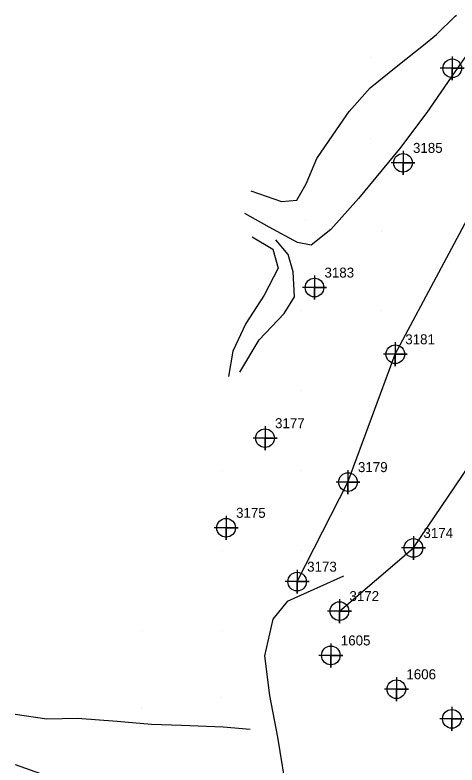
# Model space of a CAD drawing. Extents: x 2062781 to 2066835, y 358981 to 366501.
# Drawn here: x 2063958.7 to 2064069.5, y 361856.4 to 362044.4 of the extents above; entities that cross this region are included whole.
import ezdxf

# ---------------------------------------------------------------- set-up
doc = ezdxf.new("R2010")
doc.units = 0
for name, color, linetype in [('Exist DTM Breakline', 7, 'Continuous'), ('Exist DTM Breakline Cogo Number', 7, 'Continuous'), ('Exist DTM Breakline Cogo Point CELL', 7, 'Continuous'), ('Exist DTM Regular Point CELL', 7, 'Continuous'), ('Exist DTM Regular Point Cogo Number', 7, 'Continuous'), ('Exist DTM Ridgeline', 7, 'Continuous'), ('Exist DTM Ridgeline Cogo Number', 7, 'Continuous'), ('Exist DTM Ridgeline Cogo Point CELL', 7, 'Continuous'), ('PH Exist DTM Breakline', 7, 'Continuous'), ('PH Exist DTM Point', 7, 'Continuous')]:
    doc.layers.add(name, color=color, linetype=linetype)

msp = doc.modelspace()

# ---------------------------------------------------------------- linework, layer by layer
at = {"layer": 'Exist DTM Breakline'}
msp.add_lwpolyline([(2064029.46, 361902.4), (2064042.2, 361927.36), (2064054.07, 361959.4), (2064073.45, 361995.69), (2064101.12, 362020.33), (2064117.15, 362026.42)], dxfattribs=at)
at = {"layer": 'Exist DTM Breakline Cogo Point CELL'}
for points in [[(2064054.07, 361962.4), (2064054.07, 361956.4), (2064054.07, 361959.4), (2064057.07, 361959.4), (2064051.07, 361959.4)], [(2064054.07, 361962.4), (2064054.07, 361956.4), (2064054.07, 361959.4), (2064057.07, 361959.4), (2064051.07, 361959.4)], [(2064054.07, 361962.4), (2064054.07, 361956.4), (2064054.07, 361959.4), (2064057.07, 361959.4), (2064051.07, 361959.4)], [(2064042.2, 361930.36), (2064042.2, 361924.36), (2064042.2, 361927.36), (2064045.2, 361927.36), (2064039.2, 361927.36)], [(2064042.2, 361930.36), (2064042.2, 361924.36), (2064042.2, 361927.36), (2064045.2, 361927.36), (2064039.2, 361927.36)], [(2064042.2, 361930.36), (2064042.2, 361924.36), (2064042.2, 361927.36), (2064045.2, 361927.36), (2064039.2, 361927.36)], [(2064029.46, 361905.4), (2064029.46, 361899.4), (2064029.46, 361902.4), (2064032.46, 361902.4), (2064026.46, 361902.4)], [(2064029.46, 361905.4), (2064029.46, 361899.4), (2064029.46, 361902.4), (2064032.46, 361902.4), (2064026.46, 361902.4)], [(2064029.46, 361905.4), (2064029.46, 361899.4), (2064029.46, 361902.4), (2064032.46, 361902.4), (2064026.46, 361902.4)]]:
    msp.add_lwpolyline(points, dxfattribs=at)
for centre in [(2064054.07, 361959.4), (2064054.07, 361959.4), (2064054.07, 361959.4), (2064042.2, 361927.36), (2064042.2, 361927.36), (2064042.2, 361927.36), (2064029.46, 361902.4), (2064029.46, 361902.4), (2064029.46, 361902.4)]:
    msp.add_circle(centre, 2.34, dxfattribs=at)
at = {"layer": 'Exist DTM Regular Point CELL'}
for points in [[(2064068.35, 362034.08), (2064068.35, 362028.08), (2064068.35, 362031.08), (2064071.35, 362031.08), (2064065.35, 362031.08)], [(2064056, 362010.38), (2064056, 362004.38), (2064056, 362007.38), (2064059, 362007.38), (2064053, 362007.38)], [(2064033.8, 361979.12), (2064033.8, 361973.12), (2064033.8, 361976.12), (2064036.8, 361976.12), (2064030.8, 361976.12)], [(2064021.4, 361941.37), (2064021.4, 361935.37), (2064021.4, 361938.37), (2064024.4, 361938.37), (2064018.4, 361938.37)], [(2064011.63, 361918.9), (2064011.63, 361912.9), (2064011.63, 361915.9), (2064014.63, 361915.9), (2064008.63, 361915.9)], [(2064037.9, 361886.91), (2064037.9, 361880.91), (2064037.9, 361883.91), (2064040.9, 361883.91), (2064034.9, 361883.91)], [(2064054.34, 361878.43), (2064054.34, 361872.43), (2064054.34, 361875.43), (2064057.34, 361875.43), (2064051.34, 361875.43)], [(2064068.25, 361871), (2064068.25, 361865), (2064068.25, 361868), (2064071.25, 361868), (2064065.25, 361868)]]:
    msp.add_lwpolyline(points, dxfattribs=at)
for centre in [(2064068.35, 362031.08), (2064056, 362007.38), (2064033.8, 361976.12), (2064021.4, 361938.37), (2064011.63, 361915.9), (2064037.9, 361883.91), (2064054.34, 361875.43), (2064068.25, 361868)]:
    msp.add_circle(centre, 2.34, dxfattribs=at)
at = {"layer": 'Exist DTM Ridgeline'}
msp.add_lwpolyline([(2064040.06, 361895.02), (2064058.62, 361910.84), (2064072.66, 361931.62), (2064084.88, 361946.07), (2064096.39, 361965.27), (2064109.04, 361979.15), (2064128.44, 361984.19), (2064155.63, 361985.77), (2064168.96, 361977.42), (2064180.57, 361975.17)], dxfattribs=at)
at = {"layer": 'Exist DTM Ridgeline Cogo Point CELL'}
for points in [[(2064058.62, 361913.84), (2064058.62, 361907.84), (2064058.62, 361910.84), (2064061.62, 361910.84), (2064055.62, 361910.84)], [(2064058.62, 361913.84), (2064058.62, 361907.84), (2064058.62, 361910.84), (2064061.62, 361910.84), (2064055.62, 361910.84)], [(2064058.62, 361913.84), (2064058.62, 361907.84), (2064058.62, 361910.84), (2064061.62, 361910.84), (2064055.62, 361910.84)], [(2064040.06, 361898.02), (2064040.06, 361892.02), (2064040.06, 361895.02), (2064043.06, 361895.02), (2064037.06, 361895.02)], [(2064040.06, 361898.02), (2064040.06, 361892.02), (2064040.06, 361895.02), (2064043.06, 361895.02), (2064037.06, 361895.02)], [(2064040.06, 361898.02), (2064040.06, 361892.02), (2064040.06, 361895.02), (2064043.06, 361895.02), (2064037.06, 361895.02)]]:
    msp.add_lwpolyline(points, dxfattribs=at)
for centre in [(2064058.62, 361910.84), (2064058.62, 361910.84), (2064058.62, 361910.84), (2064040.06, 361895.02), (2064040.06, 361895.02), (2064040.06, 361895.02)]:
    msp.add_circle(centre, 2.34, dxfattribs=at)
at = {"layer": 'PH Exist DTM Breakline'}
for points in [[(2064017.8, 362000.4), (2064025.52, 361997.73), (2064029.41, 361998.04), (2064031.67, 362002.08), (2064034.41, 362008.49), (2064039.31, 362015.66), (2064042.46, 362020.28), (2064047.8, 362026.18), (2064054.72, 362031.82), (2064061.13, 362036.91), (2064064.39, 362039.53), (2064069.08, 362044.14), (2064069.42, 362044.44)], [(2064076.6, 362041.05), (2064068.96, 362030.17), (2064061.97, 362020.04), (2064055.1, 362010.92), (2064044.83, 361998.43), (2064037.92, 361990.68), (2064032.93, 361986.74), (2064029.56, 361987.4), (2064022.45, 361991.28), (2064016.31, 361994.67)], [(2064018.16, 361988.86), (2064023.34, 361985.71), (2064024.69, 361981.02), (2064021.19, 361974.19), (2064016.62, 361967.14), (2064013.31, 361960.21), (2064012.24, 361953.8)], [(2064015.07, 361954.92), (2064019.92, 361963.02), (2064026.16, 361969.59), (2064028.75, 361973.82), (2064028.44, 361980.02), (2064027.19, 361984.42), (2064024.11, 361988.11)], [(2064041.05, 361903.75), (2064026.97, 361897.39), (2064023.31, 361892.98), (2064021.23, 361883.8), (2064022.49, 361873.87), (2064024.56, 361863.41), (2064026.93, 361848.54)], [(2063958.73, 361869.22), (2063966.67, 361868.02), (2063974.38, 361868.17), (2063984.31, 361867.45), (2063992.89, 361866.65), (2064000.41, 361866.42), (2064010.88, 361865.98), (2064017.7, 361865.46)], [(2063958.69, 361856.52), (2063965.12, 361854.29), (2063970, 361849.19), (2063976.27, 361846.4), (2063983.34, 361846.23), (2063992.71, 361842.97), (2064001.18, 361842.42), (2064010.69, 361844.81), (2064018.76, 361849.67)]]:
    msp.add_lwpolyline(points, dxfattribs=at)
at = {"layer": 'PH Exist DTM Point'}
for p, q in [((2064047.95, 362033.85), (2064047.95, 362033.85)), ((2064047.95, 362013.47), (2064047.95, 362013.47)), ((2064031.43, 361993.3), (2064031.43, 361993.3)), ((2064050.65, 361990.27), (2064050.65, 361990.27)), ((2064030.65, 361970.27), (2064030.65, 361970.27)), ((2064050.65, 361970.27), (2064050.65, 361970.27)), ((2064030.65, 361950.27), (2064030.65, 361950.27)), ((2064010.65, 361930.27), (2064010.65, 361930.27)), ((2064030.65, 361930.27), (2064030.65, 361930.27)), ((2064010.65, 361910.27), (2064010.65, 361910.27)), ((2064030.65, 361910.27), (2064030.65, 361910.27)), ((2063990.63, 361890.24), (2063990.63, 361890.24)), ((2064010.65, 361890.27), (2064010.65, 361890.27)), ((2064010.51, 361873.38), (2064010.51, 361873.38)), ((2063990.48, 361870.93), (2063990.48, 361870.93))]:
    msp.add_line(p, q, dxfattribs=at)

# ---------------------------------------------------------------- texts
at = {"layer": 'Exist DTM Breakline Cogo Number'}
for s, p in [('3181', (2064056.57, 361961.9)), ('3181', (2064056.57, 361961.9)), ('3181', (2064056.57, 361961.9)), ('3179', (2064044.7, 361929.86)), ('3179', (2064044.7, 361929.86)), ('3179', (2064044.7, 361929.86)), ('3173', (2064031.96, 361904.9)), ('3173', (2064031.96, 361904.9)), ('3173', (2064031.96, 361904.9))]:
    msp.add_text(s, height=2.5, dxfattribs=at).set_placement(p)
at = {"layer": 'Exist DTM Regular Point Cogo Number'}
for s, p in [('3185', (2064058.5, 362009.88)), ('3185', (2064058.5, 362009.88)), ('3185', (2064058.5, 362009.88)), ('3183', (2064036.3, 361978.62)), ('3183', (2064036.3, 361978.62)), ('3183', (2064036.3, 361978.62)), ('3177', (2064023.9, 361940.87)), ('3177', (2064023.9, 361940.87)), ('3177', (2064023.9, 361940.87)), ('3175', (2064014.13, 361918.4)), ('3175', (2064014.13, 361918.4)), ('3175', (2064014.13, 361918.4)), ('1605', (2064040.4, 361886.41)), ('1605', (2064040.4, 361886.41)), ('1605', (2064040.4, 361886.41)), ('1606', (2064056.84, 361877.93)), ('1606', (2064056.84, 361877.93)), ('1606', (2064056.84, 361877.93))]:
    msp.add_text(s, height=2.5, dxfattribs=at).set_placement(p)
at = {"layer": 'Exist DTM Ridgeline Cogo Number'}
for s, p in [('3174', (2064061.12, 361913.34)), ('3174', (2064061.12, 361913.34)), ('3174', (2064061.12, 361913.34)), ('3172', (2064042.56, 361897.53)), ('3172', (2064042.56, 361897.53)), ('3172', (2064042.56, 361897.53))]:
    msp.add_text(s, height=2.5, dxfattribs=at).set_placement(p)

doc.saveas('drawing.dxf')
